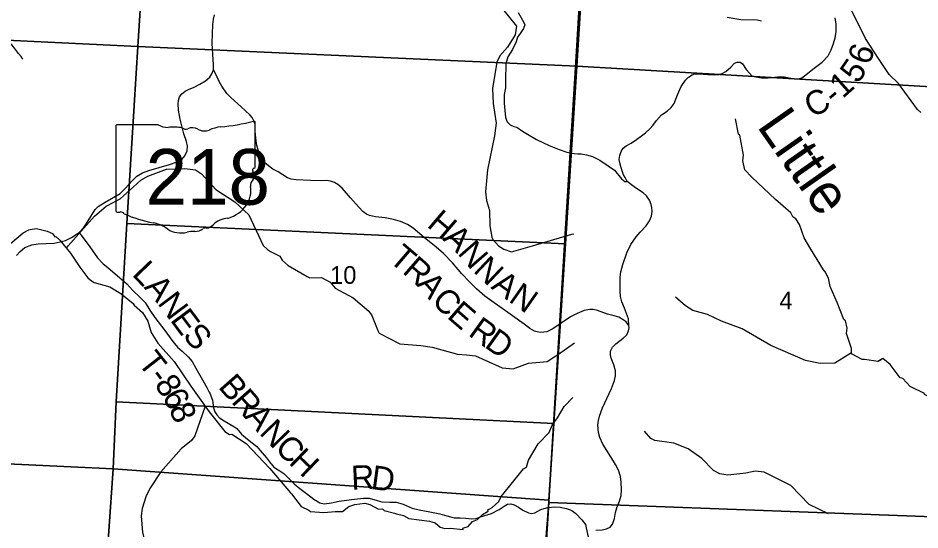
# Model space of a CAD drawing. Extents: x 1878108 to 2183446, y 146837 to 508383.
# Drawn here: x 2029722 to 2040993, y 228134 to 234528 of the extents above; entities that cross this region are included whole.
import ezdxf

# ---------------------------------------------------------------- set-up
doc = ezdxf.new("R2010")
doc.units = 0
for name, color, linetype in [('GM_X_County_Road', 7, 'Continuous'), ('GM_X_County_Road_Text', 7, 'Continuous'), ('GM_X_Minor_River', 7, 'Continuous'), ('GM_X_Minor_River_Text', 7, 'Continuous'), ('GM_X_Section', 7, 'Continuous'), ('GM_X_Section_Text', 7, 'Continuous'), ('GM_X_State_Location', 7, 'Continuous'), ('GM_X_State_Route', 7, 'Continuous'), ('GM_X_State_Shield', 7, 'Continuous'), ('GM_X_Township', 7, 'Continuous'), ('GM_X_Township_Road', 7, 'Continuous'), ('GM_X_Township_Road_Text', 7, 'Continuous')]:
    doc.layers.add(name, color=color, linetype=linetype)

msp = doc.modelspace()

# ---------------------------------------------------------------- linework, layer by layer
at = {"layer": 'GM_X_County_Road'}
for points in [[(2035971, 234599), (2036042, 234474), (2036056, 234444), (2036040, 234399), (2035998, 234337), (2035963, 234288), (2035948, 234232), (2035901, 234135), (2035844, 234042), (2035818, 233957), (2035813, 233757), (2035813, 233658), (2035798, 233574), (2035797, 233465), (2035815, 233287), (2035834, 233232), (2035871, 233193), (2035920, 233173), (2035955, 233165), (2036026, 233115), (2036089, 233077), (2036200, 233009), (2036360, 232934), (2036486, 232884), (2036582, 232853), (2036622, 232845), (2036672, 232835), (2036716, 232833)], [(2037309, 232535), (2037290, 232571), (2037259, 232658), (2037241, 232718), (2037236, 232761), (2037242, 232809), (2037260, 232861), (2037286, 232902), (2037321, 232930), (2037385, 232966), (2037452, 233010), (2037565, 233093), (2037621, 233147), (2037654, 233185), (2037700, 233247), (2037762, 233319), (2037834, 233365), (2037886, 233411), (2037921, 233461), (2037965, 233569), (2038008, 233672), (2038064, 233753), (2038099, 233791), (2038145, 233818), (2038182, 233831), (2038224, 233832), (2038341, 233823), (2038427, 233818), (2038478, 233822), (2038521, 233835), (2038566, 233860), (2038628, 233916), (2038676, 233963), (2038708, 233978), (2038745, 233975), (2038775, 233955), (2038821, 233887), (2038862, 233841), (2038898, 233803), (2038942, 233792), (2039015, 233781), (2039098, 233780), (2039215, 233792), (2039298, 233795), (2039378, 233778), (2039434, 233768), (2039477, 233769), (2039519, 233783), (2039569, 233817), (2039654, 233888), (2039772, 233979), (2039845, 234057), (2039883, 234129), (2039912, 234211), (2039933, 234282), (2039945, 234360), (2039946, 234453), (2039935, 234531)], [(2036549, 230742), (2036508, 230715), (2036491, 230703), (2036398, 230641), (2036330, 230608), (2036293, 230604), (2036248, 230600), (2036208, 230607), (2036178, 230618), (2036116, 230652), (2036047, 230705), (2035816, 230870), (2035673, 230971), (2035556, 231056), (2035453, 231147), (2035362, 231234), (2035268, 231331), (2035153, 231470), (2035041, 231588), (2034949, 231667), (2034798, 231788), (2034661, 231905), (2034588, 231951), (2034503, 231987), (2034416, 232011), (2034309, 232031), (2034188, 232043), (2034114, 232062), (2034078, 232077), (2034031, 232112), (2033981, 232166), (2033875, 232284), (2033772, 232402), (2033719, 232449), (2033675, 232475), (2033627, 232491), (2033577, 232500), (2033503, 232496), (2033377, 232497), (2033197, 232508), (2033135, 232516), (2033089, 232533), (2033033, 232569), (2032975, 232606), (2032908, 232642), (2032854, 232681), (2032807, 232720), (2032764, 232777), (2032734, 232841), (2032705, 232935), (2032692, 233029), (2032687, 233113), (2032684, 233198), (2032670, 233246), (2032649, 233285), (2032617, 233320), (2032509, 233420), (2032381, 233534), (2032333, 233586), (2032270, 233676), (2032237, 233734), (2032187, 233845), (2032163, 233883)], [(2036716, 232833), (2036761, 232832), (2036826, 232818), (2036902, 232797), (2036992, 232752), (2037096, 232680), (2037177, 232629), (2037264, 232519), (2037305, 232488), (2037334, 232488)], [(2037355, 230687), (2037349, 230770), (2037301, 230902), (2037267, 230985), (2037251, 231048), (2037247, 231121), (2037246, 231211), (2037248, 231293), (2037256, 231356), (2037281, 231451), (2037331, 231594), (2037382, 231701), (2037445, 231795), (2037497, 231855), (2037573, 231932), (2037613, 231995), (2037637, 232052), (2037648, 232111), (2037644, 232160), (2037636, 232197), (2037613, 232254), (2037578, 232306), (2037535, 232346), (2037478, 232382), (2037423, 232418), (2037334, 232488), (2037309, 232535)], [(2036941, 228132), (2037023, 228135), (2037076, 228146), (2037121, 228168), (2037151, 228206), (2037175, 228276), (2037189, 228353), (2037205, 228408), (2037238, 228495), (2037259, 228562), (2037265, 228633), (2037261, 228731), (2037252, 228801), (2037226, 228879), (2037190, 228952), (2037131, 229047), (2037030, 229204), (2036993, 229289), (2036978, 229353), (2036969, 229443), (2036976, 229501), (2036987, 229556), (2037025, 229660), (2037140, 229900), (2037175, 230001), (2037187, 230058), (2037187, 230121), (2037167, 230197), (2037133, 230280), (2037124, 230323), (2037127, 230369), (2037149, 230418), (2037193, 230460), (2037285, 230531), (2037331, 230573), (2037353, 230622), (2037359, 230657), (2037355, 230687), (2037320, 230732), (2037283, 230760), (2037229, 230792), (2037170, 230809), (2037087, 230829), (2036964, 230873), (2036911, 230886), (2036867, 230888), (2036798, 230874), (2036709, 230839), (2036627, 230794), (2036549, 230742)]]:
    msp.add_lwpolyline(points, dxfattribs=at)
at = {"layer": 'GM_X_Minor_River'}
for points in [[(2041004, 233348), (2040961, 233386), (2040725, 233710), (2040607, 233824), (2040477, 234021), (2040313, 234274), (2040097, 234710), (2040051, 234756), (2039913, 235035)], [(2035776, 234642), (2035953, 234426), (2035934, 234318), (2035841, 234163), (2035742, 234054), (2035706, 233977), (2035652, 233646), (2035660, 233461), (2035697, 233217), (2035678, 233055), (2035591, 232631), (2035565, 232359), (2035576, 232247), (2035612, 232123), (2035618, 231931), (2035642, 231789), (2035655, 231763), (2035726, 231684), (2035795, 231640), (2035890, 231609), (2036153, 231681), (2036643, 231828), (2036667, 231833)], [(2038583, 234538), (2038754, 234509), (2038959, 234506), (2039011, 234492)], [(2040472, 230237), (2040299, 230264), (2040269, 230262), (2040139, 230334), (2040137, 230400), (2040075, 230586), (2040083, 230655), (2040063, 230747), (2040043, 230763), (2039957, 230973), (2039873, 231176), (2039851, 231280), (2039807, 231360), (2039789, 231382), (2039631, 231639), (2039545, 231783), (2039487, 231950), (2039441, 232018), (2039403, 232046), (2039381, 232094), (2039187, 232262), (2038894, 232542), (2038806, 232632), (2038778, 232743), (2038787, 232815), (2038743, 233066), (2038725, 233078), (2038689, 233268)], [(2030328, 231653), (2030348, 231684), (2030678, 232052), (2030822, 232178), (2030998, 232269), (2031164, 232418), (2031255, 232505), (2031344, 232554), (2031576, 232641), (2031808, 232650), (2031939, 232630), (2032015, 232581), (2032193, 232385), (2032430, 232233), (2032605, 232069), (2032787, 231686), (2032839, 231636), (2032878, 231613), (2032994, 231555), (2033024, 231502), (2033098, 231438), (2033336, 231299)], [(2029575, 231666), (2029787, 231845), (2029856, 231883), (2029872, 231885), (2029952, 231900), (2030086, 231866), (2030152, 231838), (2030182, 231796), (2030196, 231800), (2030246, 231752), (2030376, 231592), (2030496, 231417), (2030593, 231281), (2030641, 231245), (2030673, 231223), (2030869, 231169), (2031005, 231087), (2031161, 230961), (2031175, 230943), (2031276, 230849), (2031344, 230741), (2031388, 230601), (2031468, 230466), (2031672, 230238), (2031880, 229929), (2032110, 229609), (2032308, 229363), (2032366, 229327), (2032392, 229329), (2032573, 229215), (2032869, 228902), (2033127, 228598), (2033141, 228584), (2033261, 228426), (2033358, 228382), (2033378, 228366), (2033544, 228350), (2033684, 228364), (2033776, 228363), (2033855, 228425), (2033931, 228453), (2034057, 228468), (2034119, 228452), (2034227, 228394), (2034275, 228396), (2034299, 228376), (2034428, 228344), (2034450, 228336), (2034540, 228314), (2034604, 228276), (2034864, 228243), (2034933, 228223), (2034999, 228167), (2035055, 228151), (2035121, 228155), (2035283, 228139), (2035279, 228157), (2035349, 228176), (2035400, 228240), (2035462, 228264), (2035526, 228326), (2035598, 228367), (2035594, 228383), (2035620, 228399), (2035648, 228415), (2035730, 228490), (2035761, 228552), (2035853, 228662), (2036037, 228896), (2036075, 228920), (2036100, 229004), (2036224, 229211), (2036360, 229350), (2036399, 229444), (2036463, 229533), (2036549, 229677), (2036655, 229790)], [(2033336, 231299), (2033369, 231283), (2033515, 231286), (2033621, 231227), (2033686, 231154), (2033910, 231035), (2034105, 230868), (2034143, 230813), (2034219, 230626), (2034234, 230593), (2034494, 230457), (2034756, 230436), (2034897, 230416), (2035214, 230328), (2035326, 230322), (2035437, 230308), (2035774, 230159), (2035909, 230147), (2036101, 230215), (2036333, 230236), (2036445, 230308), (2036478, 230329), (2036677, 230473)], [(2040137, 230346), (2039931, 230217), (2039747, 230211), (2039561, 230251), (2039131, 230439), (2038770, 230645), (2038514, 230743), (2038337, 230823), (2038157, 230875), (2038065, 230932), (2037938, 231040)], [(2042077, 228928), (2041961, 229005), (2041769, 229170), (2041663, 229248), (2041517, 229426), (2041501, 229428), (2041333, 229644), (2041195, 229716), (2041102, 229800), (2041048, 229824), (2041052, 229838), (2040870, 229924), (2040778, 230026), (2040744, 230032), (2040622, 230200), (2040530, 230274), (2040466, 230238), (2040513, 230264)], [(2032060, 229679), (2031930, 229308), (2031888, 229251), (2031759, 229147), (2031507, 228858), (2031376, 228664), (2031325, 228561), (2031272, 228401), (2031261, 228311), (2031277, 228102), (2031313, 227972), (2031384, 227818), (2031468, 227707)], [(2039852, 228335), (2039610, 228453), (2039378, 228689), (2039047, 228854), (2038934, 228868), (2038819, 228845), (2038593, 228820), (2038494, 228835), (2038415, 228876), (2038268, 229027), (2038098, 229149), (2037919, 229219), (2037680, 229252), (2037631, 229278), (2037552, 229369)]]:
    msp.add_lwpolyline(points, dxfattribs=at)
at = {"layer": 'GM_X_Section'}
for points in [[(2026001, 239844), (2031567, 239568), (2031220, 234172), (2025688, 234438)], [(2031567, 239568), (2037039, 239291), (2036706, 233925), (2031220, 234172)], [(2037039, 239291), (2042638, 239086), (2042277, 233603), (2036706, 233925)], [(2025688, 234438), (2031220, 234172), (2031083, 231960), (2030950, 229735), (2030910, 228899), (2027742, 229049), (2025381, 229188), (2025382, 229207), (2025432, 230150), (2025553, 232333)], [(2031220, 234172), (2036706, 233925), (2036563, 231706), (2031083, 231960)], [(2042277, 233603), (2041943, 228267), (2036355, 228477), (2036357, 228504), (2036419, 229463), (2036563, 231706), (2036706, 233925)], [(2036563, 231706), (2036419, 229463), (2030950, 229735), (2031083, 231960)], [(2030950, 229735), (2036419, 229463), (2036357, 228504), (2030910, 228899)], [(2030910, 228899), (2030822, 227644), (2030446, 227648), (2030240, 224596), (2027476, 224730), (2027742, 229049)], [(2036357, 228504), (2036355, 228477), (2036280, 227277), (2033343, 227475), (2030822, 227644), (2030910, 228899)], [(2036355, 228477), (2041943, 228267), (2041598, 222717), (2040585, 222757), (2039540, 222774), (2038466, 222827), (2037467, 222878), (2036610, 222920), (2036010, 222952), (2036280, 227277)]]:
    msp.add_lwpolyline(points, close=True, dxfattribs=at)
at = {"layer": 'GM_X_State_Route'}
msp.add_lwpolyline([(2029705, 231563), (2029747, 231611), (2029809, 231663), (2029896, 231696), (2029974, 231708), (2030075, 231711), (2030174, 231716), (2030249, 231732), (2030314, 231751), (2030391, 231786), (2030485, 231851), (2030544, 231912), (2030600, 231995), (2030688, 232137), (2030724, 232175), (2030810, 232227), (2030997, 232335), (2031058, 232396), (2031151, 232500), (2031207, 232551), (2031278, 232595), (2031355, 232623), (2031617, 232698), (2031709, 232731), (2031769, 232763), (2031807, 232807), (2031834, 232871), (2031838, 232928), (2031827, 232987), (2031796, 233080), (2031748, 233263), (2031729, 233378), (2031724, 233458), (2031727, 233500), (2031739, 233542), (2031769, 233582), (2031811, 233616), (2031854, 233637), (2031924, 233666), (2031993, 233702), (2032065, 233744), (2032118, 233789), (2032144, 233832), (2032163, 233883), (2032166, 233948), (2032155, 234074), (2032150, 234216), (2032157, 234447), (2032164, 234515), (2032179, 234570)], dxfattribs=at)
at = {"layer": 'GM_X_State_Shield'}
for p, q in [((2031473, 233196), (2030963, 233196)), ((2032686, 232670), (2032686, 233222)), ((2030946, 233178), (2030946, 232121)), ((2032686, 232670), (2032686, 232670))]:
    msp.add_line(p, q, dxfattribs=at)
for centre, major_axis, start_param, end_param in [((2030966, 233180), (20.2, 0), 1.712693, 3.28349), ((2031594, 233319), (196, 0), 4.042523, 4.731795), ((2032066, 234637), (1845, 0), 4.814394, 5.042369), ((2032667, 233225), (19.4, 0), 6.141152, 7.989035), ((2031659, 232603), (702, 0), 1.404758, 1.657858), ((2031818, 233186), (56.4, 0), 3.836095, 5.185415), ((2031901, 233064), (117, 0), 0.950623, 2.079405), ((2032053, 233231), (141, 0), 4.081561, 5.145723), ((2032302, 232874), (371, 0), 1.699011, 2.107814), ((2032682, 232629), (30, 0), 1.883978, 3.671073), ((2032666, 232668), (20.7, 0), 5.05454, 6.418171), ((2032491, 232559), (180, 0), 5.934695, 6.695948), ((2032170, 232368), (462, 0), 5.101752, 6.440018), ((2032756, 232438), (131, 0), 2.387724, 3.262537), ((2030966, 232119), (20.3, 0), 3.00124, 4.508301), ((2030969, 232227), (155, 0), 4.665946, 4.897461), ((2031001, 232061), (56, 0), 0.519207, 1.627899), ((2031708, 233010), (1333, 0), 4.195997, 4.488961), ((2031310, 231647), (417, 0), 0.823519, 1.323587), ((2032364, 231825), (253, 0), 1.647645, 2.488434), ((2031761, 232055), (265, 0), 4.026481, 4.996735), ((2031914, 231690), (217, 0), 1.495662, 1.94098), ((2031933, 231976), (141, 0), 4.691044, 5.507374), ((2032061, 231874), (39.7, 0), 1.147584, 2.315152), ((2032044, 232019), (149, 0), 4.937069, 5.64225)]:
    msp.add_ellipse(centre, major_axis=major_axis, ratio=0.8, start_param=start_param, end_param=end_param, dxfattribs=at)
at = {"layer": 'GM_X_Township'}
for points in [[(2008888, 227673), (2009016, 229762), (2009205, 232852), (2009662, 240602), (2009980, 246018), (2011114, 245960), (2015331, 245746), (2020898, 245447), (2023806, 245304), (2027678, 245113), (2029007, 245047), (2031899, 244904), (2033284, 244833), (2037354, 244623), (2037219, 242509), (2037025, 239474), (2036924, 237810), (2036687, 233905), (2036623, 232849), (2036493, 230741), (2036351, 228419), (2036235, 226946)], [(2041168, 217981), (2040086, 218175), (2039954, 218181), (2038960, 218124), (2037622, 218100), (2036688, 217942), (2036361, 217795), (2036102, 217475), (2035896, 217629), (2035631, 217639), (2035667, 218204), (2036020, 223625), (2036235, 226946), (2036351, 228419), (2036493, 230741), (2036623, 232849), (2036687, 233905), (2036924, 237810), (2037025, 239474), (2037219, 242509), (2037354, 244623), (2042339, 244401)]]:
    msp.add_lwpolyline(points, dxfattribs=at)
at = {"layer": 'GM_X_Township_Road'}
for points in [[(2029782, 234015), (2029763, 234047), (2029730, 234084), (2029677, 234151), (2029643, 234193), (2029599, 234221), (2029540, 234235), (2029354, 234241), (2029289, 234245), (2029216, 234267), (2029143, 234290), (2029103, 234306), (2029092, 234329), (2029111, 234377), (2029148, 234455), (2029158, 234506)], [(2030485, 231851), (2030620, 231669), (2030715, 231533), (2030785, 231458), (2030844, 231410), (2030993, 231282), (2031080, 231209), (2031157, 231124), (2031240, 231046), (2031309, 230975), (2031369, 230880), (2031433, 230789), (2031557, 230624), (2031658, 230489), (2031717, 230418), (2031772, 230369), (2031850, 230295), (2031900, 230239), (2031944, 230153), (2031995, 230067), (2032080, 229912), (2032111, 229856)], [(2032111, 229856), (2032119, 229842), (2032151, 229756), (2032167, 229658), (2032181, 229611), (2032205, 229573), (2032240, 229536), (2032300, 229495), (2032421, 229425), (2032456, 229402), (2032515, 229331), (2032589, 229266), (2032706, 229177), (2032750, 229128), (2032827, 229033), (2032878, 228966)], [(2032878, 228966), (2032884, 228958), (2032919, 228917), (2032992, 228873), (2033045, 228840), (2033173, 228710), (2033242, 228651), (2033328, 228588), (2033420, 228517), (2033494, 228473), (2033548, 228458), (2033639, 228473), (2033737, 228495), (2033890, 228514), (2034039, 228532), (2034110, 228531), (2034210, 228503), (2034269, 228487), (2034369, 228479), (2034446, 228481), (2034537, 228455), (2034646, 228406), (2034733, 228385), (2034869, 228360), (2034993, 228336), (2035079, 228308), (2035171, 228286), (2035247, 228284), (2035318, 228282), (2035389, 228271), (2035449, 228276), (2035500, 228298), (2035639, 228341), (2035734, 228389), (2035797, 228431), (2035838, 228455), (2035882, 228460), (2035923, 228449), (2035975, 228418), (2036029, 228381), (2036102, 228347), (2036141, 228339), (2036181, 228349), (2036256, 228391), (2036327, 228408)], [(2036327, 228408), (2036342, 228412), (2036350, 228413), (2036426, 228424), (2036496, 228419), (2036576, 228401), (2036643, 228375), (2036691, 228341), (2036769, 228261), (2036814, 228201), (2036838, 228083), (2036853, 228035)]]:
    msp.add_lwpolyline(points, dxfattribs=at)

# ---------------------------------------------------------------- texts
at = {"layer": 'GM_X_County_Road_Text'}
for s, rotation, p in [('6', 71.0324, (2040363, 233929)), ('5', 55.3666, (2040218, 233697)), ('1', 41.5097, (2040027, 233515)), ('C', 26.6261, (2039643, 233277)), ('-', 40.4737, (2039929, 233431)), ('H', 319.4556, (2034820, 231931)), ('A', 316.9297, (2035018, 231762)), ('N', 310.932, (2035205, 231587)), ('T', 319.5063, (2034344, 231497)), ('R', 318.886, (2034514, 231352)), ('N', 316.5339, (2035400, 231365)), ('A', 311.2869, (2034692, 231197)), ('A', 323.4664, (2035622, 231158)), ('N', 324.9857, (2035841, 230995)), ('C', 314.4447, (2034878, 230986)), ('E', 319.17, (2035071, 230791)), ('R', 324.1743, (2035336, 230571)), ('D', 324.6199, (2035538, 230425))]:
    msp.add_text(s, height=300, rotation=rotation, dxfattribs=at).set_placement(p)
at = {"layer": 'GM_X_Minor_River_Text'}
msp.add_text('Little', height=500, rotation=304.9993, dxfattribs=at).set_placement((2038947, 233178))
at = {"layer": 'GM_X_Section_Text'}
for s, p in [('10', (2033622, 231208)), ('4', (2039236, 230888))]:
    msp.add_text(s, height=221, rotation=0, dxfattribs=at).set_placement(p)
at = {"layer": 'GM_X_State_Location'}
for s in ['s', 'r']:
    msp.add_text(s, height=1, dxfattribs=at).set_placement((2031797, 232580))
msp.add_text('218', height=1, rotation=0, dxfattribs=at).set_placement((2031444, 232507))
at = {"layer": 'GM_X_State_Shield'}
msp.add_text('218', height=696.1, dxfattribs=at).set_placement((2031317, 232196))
at = {"layer": 'GM_X_Township_Road_Text'}
for s, rotation, p in [('L', 313.7196, (2031136, 231321)), ('A', 310.7937, (2031288, 231162)), ('N', 306.8054, (2031457, 230966)), ('E', 306.7165, (2031615, 230755)), ('S', 312.0447, (2031769, 230552)), ('T', 308.0554, (2031210, 230221)), ('-', 306.8199, (2031348, 230046)), ('8', 303.4072, (2031419, 229951)), ('B', 311.3477, (2032214, 229917)), ('6', 298.8464, (2031517, 229802)), ('R', 311.3464, (2032377, 229732)), ('8', 293.6243, (2031603, 229647)), ('A', 311.6869, (2032541, 229545)), ('N', 314.0513, (2032726, 229338)), ('C', 315.9732, (2032917, 229141)), ('H', 316.1221, (2033095, 228969)), ('R', 2.5241, (2033891, 228636)), ('D', 352.274, (2034123, 228647))]:
    msp.add_text(s, height=300, rotation=rotation, dxfattribs=at).set_placement(p)

doc.saveas('drawing.dxf')
